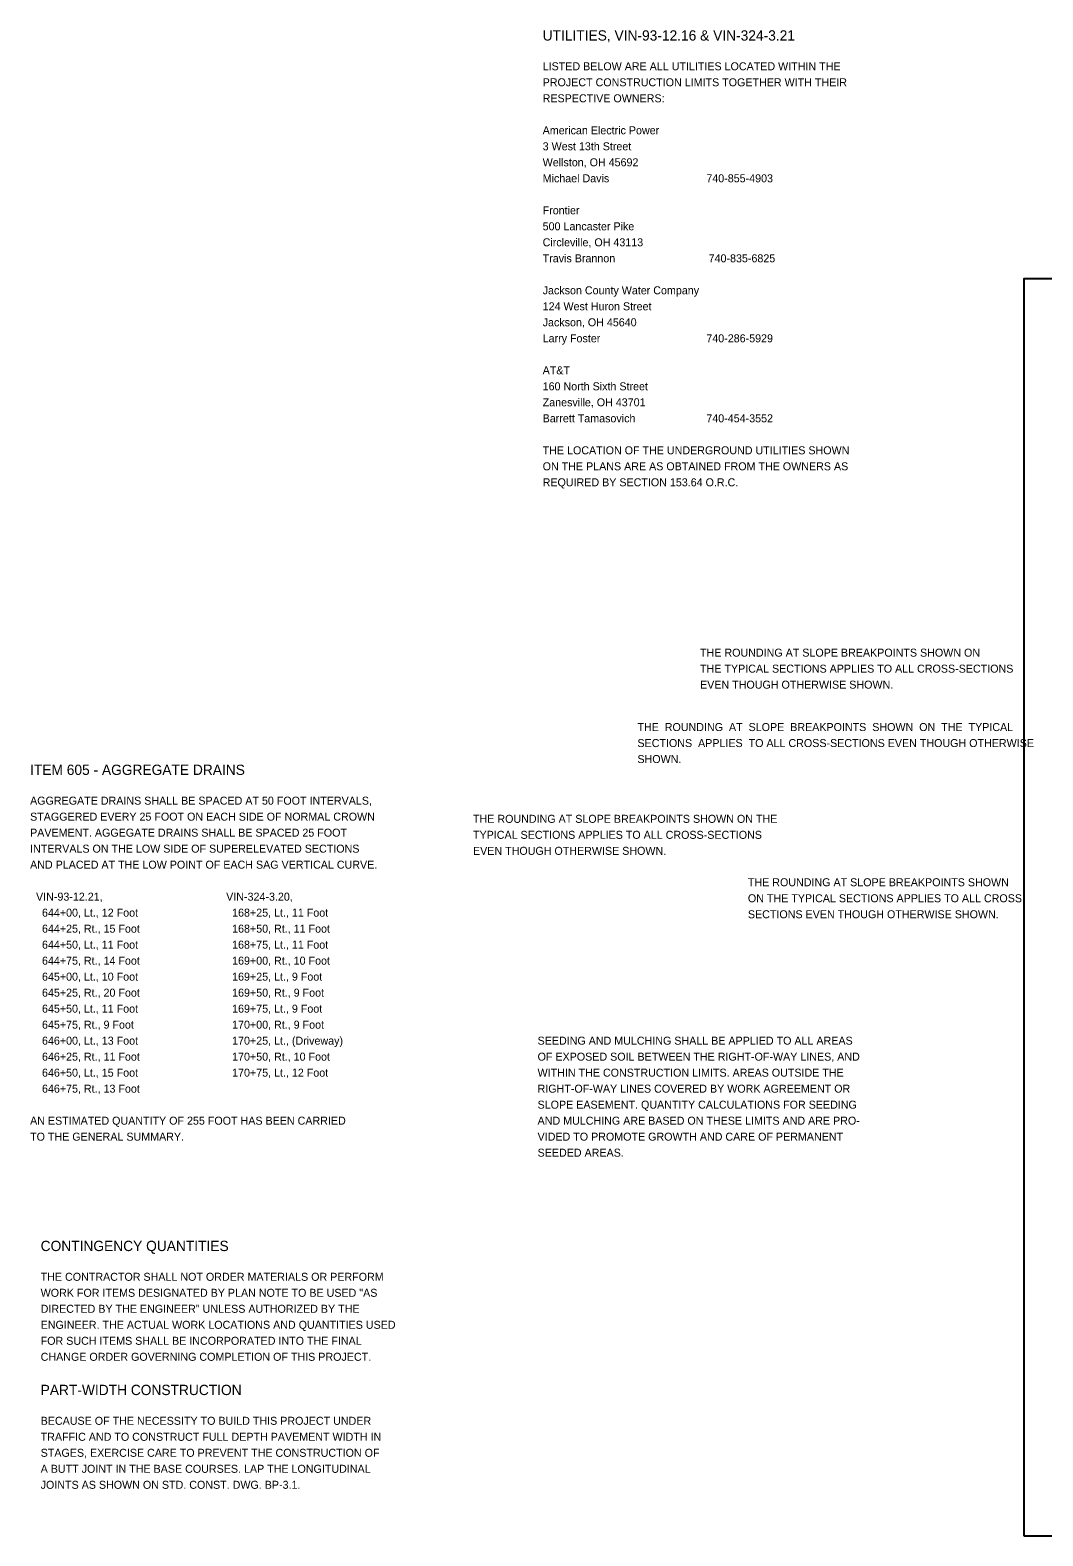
# Model space of a CAD drawing. Extents: x -17 to 718, y -174 to 36.
# Drawn here: x -17.39 to 0.34, y 0 to 26.35 of the extents above; entities that cross this region are included whole.
import ezdxf

# ---------------------------------------------------------------- set-up
doc = ezdxf.new("R2010")
doc.units = 0
doc.layers.add('SH_Border', color=7, linetype='Continuous')
doc.layers.add('SH_Text', color=7, linetype='Continuous')

msp = doc.modelspace()

# ---------------------------------------------------------------- linework, layer by layer
at = {"layer": 'SH_Border'}
msp.add_lwpolyline([(0, 0), (34, 0), (34, 22), (0, 22)], close=True, dxfattribs=at)

# ---------------------------------------------------------------- texts
at = {"layer": 'SH_Text'}
for s, height, p in [('UTILITIES, VIN-93-12.16 & VIN-324-3.21', 0.18, (-8.417, 26.167)), ('LISTED BELOW ARE ALL UTILITIES LOCATED WITHIN THE', 0.14, (-8.417, 25.647)), ('PROJECT CONSTRUCTION LIMITS TOGETHER WITH THEIR', 0.14, (-8.417, 25.367)), ('RESPECTIVE OWNERS:', 0.14, (-8.417, 25.087)), ('American Electric Power', 0.14, (-8.417, 24.527)), ('3 West 13th Street', 0.14, (-8.417, 24.247)), ('Wellston, OH 45692', 0.14, (-8.417, 23.967)), ('Michael Davis', 0.14, (-8.417, 23.687)), ('            740-855-4903', 0.14, (-6.177, 23.687)), ('Frontier', 0.14, (-8.417, 23.127)), ('500 Lancaster Pike', 0.14, (-8.417, 22.847)), ('Circleville, OH 43113', 0.14, (-8.417, 22.567)), ('Travis Brannon', 0.14, (-8.417, 22.287)), ('  740-835-6825', 0.14, (-5.617, 22.287)), ('Jackson County Water Company', 0.14, (-8.417, 21.727)), ('124 West Huron Street', 0.14, (-8.417, 21.447)), ('Jackson, OH 45640', 0.14, (-8.417, 21.167)), ('Larry Foster', 0.14, (-8.417, 20.887)), ('            740-286-5929', 0.14, (-6.177, 20.887)), ('AT&T', 0.14, (-8.417, 20.327)), ('160 North Sixth Street', 0.14, (-8.417, 20.047)), ('Zanesville, OH 43701', 0.14, (-8.417, 19.767)), ('Barrett Tamasovich', 0.14, (-8.417, 19.487)), ('            740-454-3552', 0.14, (-6.177, 19.487)), ('THE LOCATION OF THE UNDERGROUND UTILITIES SHOWN', 0.14, (-8.417, 18.927)), ('ON THE PLANS ARE AS OBTAINED FROM THE OWNERS AS', 0.14, (-8.417, 18.647)), ('REQUIRED BY SECTION 153.64 O.R.C.', 0.14, (-8.417, 18.367)), ('THE ROUNDING AT SLOPE BREAKPOINTS SHOWN ON', 0.14, (-5.663, 15.386)), ('THE TYPICAL SECTIONS APPLIES TO ALL CROSS-SECTIONS', 0.14, (-5.663, 15.106)), ('EVEN THOUGH OTHERWISE SHOWN.', 0.14, (-5.663, 14.826)), ('THE  ROUNDING  AT  SLOPE  BREAKPOINTS  SHOWN  ON  THE  TYPICAL', 0.14, (-6.759, 14.084)), ('SECTIONS  APPLIES  TO ALL CROSS-SECTIONS EVEN THOUGH OTHERWISE', 0.14, (-6.759, 13.804)), ('ITEM 605 - AGGREGATE DRAINS', 0.18, (-17.386, 13.316)), ('SHOWN.', 0.14, (-6.759, 13.524)), ('AGGREGATE DRAINS SHALL BE SPACED AT 50 FOOT INTERVALS,', 0.14, (-17.386, 12.796)), ('STAGGERED EVERY 25 FOOT ON EACH SIDE OF NORMAL CROWN', 0.14, (-17.386, 12.516)), ('THE ROUNDING AT SLOPE BREAKPOINTS SHOWN ON THE', 0.14, (-9.636, 12.478)), ('PAVEMENT. AGGEGATE DRAINS SHALL BE SPACED 25 FOOT', 0.14, (-17.386, 12.236)), ('TYPICAL SECTIONS APPLIES TO ALL CROSS-SECTIONS', 0.14, (-9.636, 12.198)), ('INTERVALS ON THE LOW SIDE OF SUPERELEVATED SECTIONS', 0.14, (-17.386, 11.956)), ('EVEN THOUGH OTHERWISE SHOWN.', 0.14, (-9.636, 11.918)), ('AND PLACED AT THE LOW POINT OF EACH SAG VERTICAL CURVE.', 0.14, (-17.386, 11.676)), ('THE ROUNDING AT SLOPE BREAKPOINTS SHOWN', 0.14, (-4.826, 11.368)), ('  VIN-93-12.21,', 0.14, (-17.386, 11.116)), ('VIN-324-3.20,', 0.14, (-13.955, 11.116)), ('ON THE TYPICAL SECTIONS APPLIES TO ALL CROSS', 0.14, (-4.826, 11.088)), ('    644+00, Lt., 12 Foot', 0.14, (-17.386, 10.836)), ('  168+25, Lt., 11 Foot', 0.14, (-13.955, 10.836)), ('SECTIONS EVEN THOUGH OTHERWISE SHOWN.', 0.14, (-4.826, 10.808)), ('    644+25, Rt., 15 Foot', 0.14, (-17.386, 10.556)), ('  168+50, Rt., 11 Foot', 0.14, (-13.955, 10.556)), ('    644+50, Lt., 11 Foot', 0.14, (-17.386, 10.276)), ('  168+75, Lt., 11 Foot', 0.14, (-13.955, 10.276)), ('    644+75, Rt., 14 Foot', 0.14, (-17.386, 9.996)), ('  169+00, Rt., 10 Foot', 0.14, (-13.955, 9.996)), ('    645+00, Lt., 10 Foot', 0.14, (-17.386, 9.716)), ('  169+25, Lt., 9 Foot', 0.14, (-13.955, 9.716)), ('    645+25, Rt., 20 Foot', 0.14, (-17.386, 9.436)), ('  169+50, Rt., 9 Foot', 0.14, (-13.955, 9.436)), ('    645+50, Lt., 11 Foot', 0.14, (-17.386, 9.156)), ('  169+75, Lt., 9 Foot', 0.14, (-13.955, 9.156)), ('    645+75, Rt., 9 Foot', 0.14, (-17.386, 8.876)), ('  170+00, Rt., 9 Foot', 0.14, (-13.955, 8.876)), ('    646+00, Lt., 13 Foot', 0.14, (-17.386, 8.596)), ('  170+25, Lt., (Driveway)', 0.14, (-13.955, 8.596)), ('SEEDING AND MULCHING SHALL BE APPLIED TO ALL AREAS', 0.14, (-8.506, 8.596)), ('    646+25, Rt., 11 Foot', 0.14, (-17.386, 8.316)), ('  170+50, Rt., 10 Foot', 0.14, (-13.955, 8.316)), ('OF EXPOSED SOIL BETWEEN THE RIGHT-OF-WAY LINES, AND', 0.14, (-8.506, 8.316)), ('    646+50, Lt., 15 Foot', 0.14, (-17.386, 8.036)), ('  170+75, Lt., 12 Foot', 0.14, (-13.955, 8.036)), ('WITHIN THE CONSTRUCTION LIMITS. AREAS OUTSIDE THE', 0.14, (-8.506, 8.036)), ('    646+75, Rt., 13 Foot', 0.14, (-17.386, 7.756)), ('RIGHT-OF-WAY LINES COVERED BY WORK AGREEMENT OR', 0.14, (-8.506, 7.756)), ('SLOPE EASEMENT. QUANTITY CALCULATIONS FOR SEEDING', 0.14, (-8.506, 7.476)), ('AN ESTIMATED QUANTITY OF 255 FOOT HAS BEEN CARRIED', 0.14, (-17.386, 7.196)), ('AND MULCHING ARE BASED ON THESE LIMITS AND ARE PRO-', 0.14, (-8.506, 7.196)), ('TO THE GENERAL SUMMARY.', 0.14, (-17.386, 6.916)), ('VIDED TO PROMOTE GROWTH AND CARE OF PERMANENT', 0.14, (-8.506, 6.916)), ('SEEDED AREAS.', 0.14, (-8.506, 6.636)), ('CONTINGENCY QUANTITIES', 0.18, (-17.201, 4.984)), ('THE CONTRACTOR SHALL NOT ORDER MATERIALS OR PERFORM', 0.14, (-17.201, 4.464)), ('WORK FOR ITEMS DESIGNATED BY PLAN NOTE TO BE USED "AS', 0.14, (-17.201, 4.184)), ('DIRECTED BY THE ENGINEER" UNLESS AUTHORIZED BY THE', 0.14, (-17.201, 3.904)), ('ENGINEER. THE ACTUAL WORK LOCATIONS AND QUANTITIES USED', 0.14, (-17.201, 3.624)), ('FOR SUCH ITEMS SHALL BE INCORPORATED INTO THE FINAL', 0.14, (-17.201, 3.344)), ('CHANGE ORDER GOVERNING COMPLETION OF THIS PROJECT.', 0.14, (-17.201, 3.064)), ('PART-WIDTH CONSTRUCTION', 0.18, (-17.201, 2.464)), ('BECAUSE OF THE NECESSITY TO BUILD THIS PROJECT UNDER', 0.14, (-17.201, 1.944)), ('TRAFFIC AND TO CONSTRUCT FULL DEPTH PAVEMENT WIDTH IN', 0.14, (-17.201, 1.664)), ('STAGES, EXERCISE CARE TO PREVENT THE CONSTRUCTION OF', 0.14, (-17.201, 1.384)), ('A BUTT JOINT IN THE BASE COURSES. LAP THE LONGITUDINAL', 0.14, (-17.201, 1.104)), ('JOINTS AS SHOWN ON STD. CONST. DWG. BP-3.1.', 0.14, (-17.201, 0.824))]:
    msp.add_text(s, height=height, dxfattribs=at).set_placement(p)

doc.saveas('drawing.dxf')
